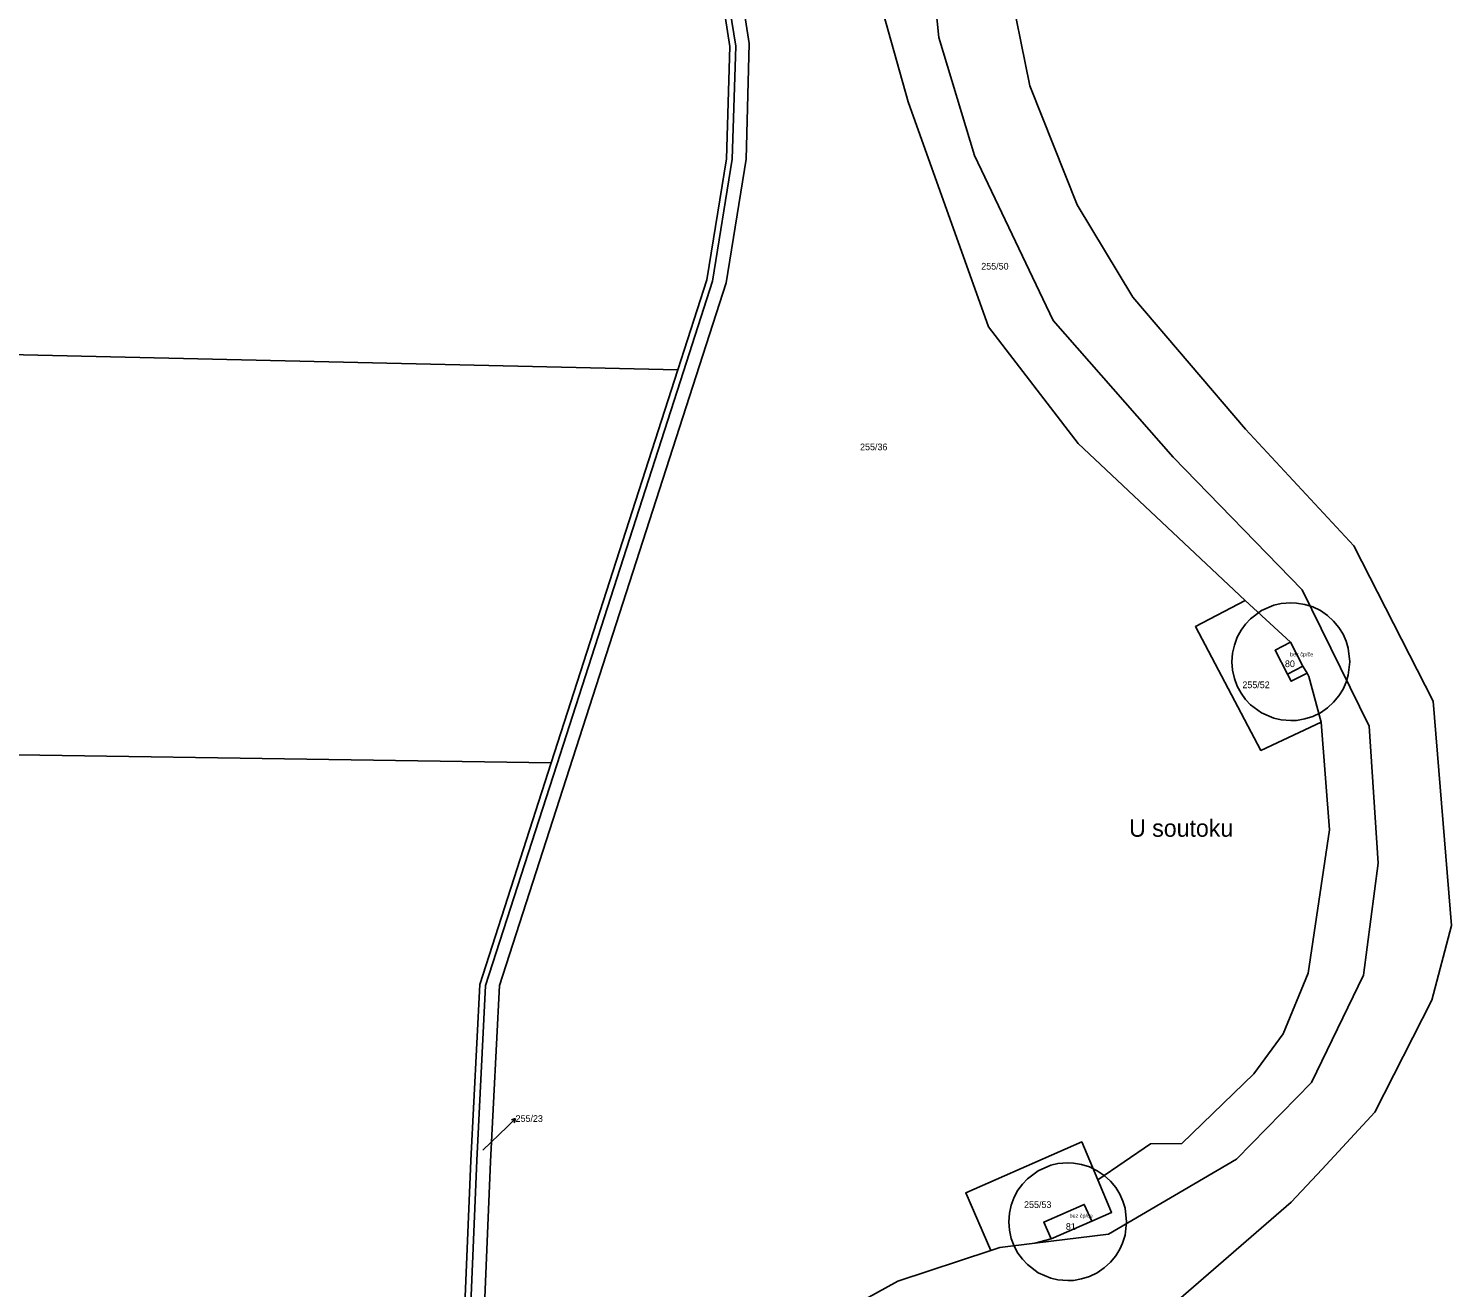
# Model space of a CAD drawing. Extents: x -882150 to -879379, y -1022570 to -1019819.
# Drawn here: x -880638.1 to -880276, y -1021896.3 to -1021575.9 of the extents above; entities that cross this region are included whole.
import ezdxf

# ---------------------------------------------------------------- set-up
doc = ezdxf.new("R2010")
doc.units = 0
for name, color, linetype in [('Definiční body', 7, 'Continuous'), ('Hranice parcel', 7, 'Continuous'), ('Parcelní čísla', 7, 'Continuous'), ('Polygon budovy', 7, 'Continuous'), ('Pop  PČ popisy', 7, 'Continuous'), ('Vnitřní kresba', 7, 'Continuous')]:
    doc.layers.add(name, color=color, linetype=linetype)

msp = doc.modelspace()

# ---------------------------------------------------------------- linework, layer by layer
at = {"layer": 'Hranice parcel'}
for p, q in [((-880472.9, -1021662.8), (-880505.13, -1021762.84)), ((-880316.92, -1021732.11), (-880328.46, -1021721.51)), ((-880275.96, -1021804.23), (-880280.95, -1021823.18)), ((-880377.84, -1021883.98), (-880367.53, -1021879.47)), ((-880377.84, -1021883.98), (-880382, -1021885.04))]:
    msp.add_line(p, q, dxfattribs=at)
for points in [[(-880533.86, -1022007.05), (-880523.29, -1021950.58), (-880522.43, -1021909.12), (-880520.53, -1021864.27), (-880518.3, -1021819.45), (-880460.57, -1021640.65), (-880455.51, -1021609.22), (-880454.71, -1021579.75), (-880473.1, -1021460.72)], [(-880403.68, -1021494.04), (-880408.13, -1021519.01), (-880409.49, -1021548.16), (-880406.41, -1021578.18), (-880397.35, -1021608.26), (-880377.39, -1021650.23), (-880346.77, -1021685.06), (-880313.96, -1021718.82), (-880296.93, -1021753.52), (-880294.62, -1021788.33), (-880298.33, -1021816.85), (-880311.6, -1021844.17), (-880330.67, -1021863.71), (-880363.25, -1021882.74), (-880382, -1021885.04)], [(-880466.28, -1021537.91), (-880459.65, -1021580.52), (-880460.51, -1021609.07), (-880465.51, -1021639.85), (-880472.9, -1021662.8)], [(-880275.96, -1021804.23), (-880280.6, -1021747.13), (-880300.81, -1021707.6), (-880328.37, -1021677.93), (-880357.11, -1021644.33), (-880371.23, -1021620.81), (-880383.32, -1021590.53), (-880388.97, -1021562.43)], [(-880328.46, -1021721.51), (-880371.01, -1021681.52), (-880393.83, -1021651.84), (-880414.22, -1021594.55), (-880422.16, -1021566.44)], [(-880472.9, -1021662.8), (-880672.83, -1021658.19), (-880872.75, -1021653.59)], [(-880328.46, -1021721.51), (-880341.15, -1021728.13), (-880324.49, -1021759.67), (-880309.1, -1021752.44)], [(-880316.92, -1021732.11), (-880320.86, -1021734.17), (-880317.71, -1021740.23), (-880316.75, -1021742.03), (-880312.73, -1021740.03)], [(-880312.73, -1021740.03), (-880313.77, -1021738.18), (-880316.92, -1021732.11)], [(-880309.1, -1021752.44), (-880312.25, -1021740.86), (-880312.73, -1021740.03)], [(-880365.98, -1021868.96), (-880352.57, -1021859.77), (-880344.62, -1021859.66), (-880326.26, -1021841.92), (-880318.82, -1021831.77), (-880312.45, -1021816.35), (-880307.02, -1021779.9), (-880309.1, -1021752.44)], [(-880889.89, -1021756.99), (-880697.51, -1021759.91), (-880505.13, -1021762.84)], [(-880505.13, -1021762.84), (-880523.29, -1021819.2), (-880525.52, -1021864.02), (-880527.43, -1021908.91), (-880528.29, -1021950.47), (-880532.51, -1021972.91)], [(-880280.95, -1021823.18), (-880295.5, -1021851.75), (-880308.92, -1021866.24)], [(-880393.19, -1021886.89), (-880399.61, -1021872.28), (-880370.08, -1021859.3), (-880365.98, -1021868.96)], [(-880308.92, -1021866.24), (-880316.75, -1021874.64), (-880345.49, -1021899.44), (-880362.19, -1021905.21), (-880391.36, -1021908.72), (-880413.46, -1021915.14), (-880439.14, -1021932.52), (-880458.37, -1021949.23)], [(-880365.98, -1021868.96), (-880362.47, -1021877.24), (-880367.53, -1021879.47)], [(-880367.53, -1021879.47), (-880369.45, -1021875.18), (-880379.73, -1021879.68), (-880377.84, -1021883.98)], [(-880481.62, -1021946.61), (-880466.63, -1021928.82), (-880438.87, -1021906.81), (-880416.85, -1021894.75), (-880393.19, -1021886.89)], [(-880382, -1021885.04), (-880390.89, -1021886.13), (-880393.19, -1021886.89)]]:
    msp.add_lwpolyline(points, dxfattribs=at)
at = {"layer": 'Polygon budovy'}
for points in [[(-880320.86, -1021734.17), (-880317.71, -1021740.23), (-880313.77, -1021738.18), (-880316.92, -1021732.11)], [(-880379.73, -1021879.68), (-880377.84, -1021883.98), (-880367.53, -1021879.47), (-880369.45, -1021875.18)]]:
    msp.add_lwpolyline(points, close=True, dxfattribs=at)
at = {"layer": 'Pop  PČ popisy'}
for p, q in [((-880516.33, -1021855.42), (-880514.171, -1021853.335)), ((-880514.171, -1021853.335), (-880515.24, -1021853.671)), ((-880514.171, -1021853.335), (-880514.544, -1021854.391)), ((-880522.49, -1021861.38), (-880516.33, -1021855.42))]:
    msp.add_line(p, q, dxfattribs=at)
at = {"layer": 'Vnitřní kresba'}
for p, q in [((-880458.15, -1021580.43), (-880476.6, -1021461.91)), ((-880459.01, -1021609.22), (-880458.15, -1021580.43)), ((-880464.05, -1021640.2), (-880459.01, -1021609.22)), ((-880471.47, -1021663.26), (-880464.05, -1021640.2)), ((-880503.7, -1021763.3), (-880471.47, -1021663.26)), ((-880327.1, -1021726.13), (-880324.34, -1021724.08)), ((-880324.34, -1021724.08), (-880321.18, -1021722.71)), ((-880321.18, -1021722.71), (-880319.36, -1021722.28)), ((-880319.36, -1021722.28), (-880316.84, -1021722.07)), ((-880316.84, -1021722.07), (-880315.39, -1021722.14)), ((-880315.39, -1021722.14), (-880313.32, -1021722.49)), ((-880313.32, -1021722.49), (-880311.28, -1021723.14)), ((-880311.28, -1021723.14), (-880309.34, -1021724.08)), ((-880309.34, -1021724.08), (-880307.55, -1021725.29)), ((-880329.53, -1021729.08), (-880328.38, -1021727.49)), ((-880328.38, -1021727.49), (-880327.1, -1021726.13)), ((-880307.55, -1021725.29), (-880305.97, -1021726.73)), ((-880305.97, -1021726.73), (-880304.64, -1021728.35)), ((-880331.23, -1021732.83), (-880330.5, -1021730.87)), ((-880330.5, -1021730.87), (-880329.53, -1021729.08)), ((-880304.64, -1021728.35), (-880303.57, -1021730.08)), ((-880303.57, -1021730.08), (-880302.77, -1021731.86)), ((-880331.84, -1021737.07), (-880331.69, -1021734.92)), ((-880331.69, -1021734.92), (-880331.23, -1021732.83)), ((-880302.77, -1021731.86), (-880302.23, -1021733.65)), ((-880302.23, -1021733.65), (-880301.84, -1021737.07)), ((-880331.69, -1021739.22), (-880331.84, -1021737.07)), ((-880317.71, -1021740.23), (-880313.77, -1021738.18)), ((-880301.84, -1021737.07), (-880302.23, -1021740.49)), ((-880331.23, -1021741.31), (-880331.69, -1021739.22)), ((-880330.5, -1021743.27), (-880331.23, -1021741.31)), ((-880302.77, -1021742.28), (-880303.57, -1021744.07)), ((-880302.23, -1021740.49), (-880302.77, -1021742.28)), ((-880329.53, -1021745.06), (-880330.5, -1021743.27)), ((-880328.38, -1021746.65), (-880329.53, -1021745.06)), ((-880304.64, -1021745.8), (-880305.97, -1021747.41)), ((-880303.57, -1021744.07), (-880304.64, -1021745.8)), ((-880327.1, -1021748.01), (-880328.38, -1021746.65)), ((-880324.34, -1021750.06), (-880327.1, -1021748.01)), ((-880307.55, -1021748.85), (-880309.34, -1021750.06)), ((-880305.97, -1021747.41), (-880307.55, -1021748.85)), ((-880321.18, -1021751.43), (-880324.34, -1021750.06)), ((-880319.36, -1021751.86), (-880321.18, -1021751.43)), ((-880316.84, -1021752.07), (-880319.36, -1021751.86)), ((-880315.39, -1021752), (-880316.84, -1021752.07)), ((-880313.32, -1021751.65), (-880315.39, -1021752)), ((-880311.28, -1021751), (-880313.32, -1021751.65)), ((-880309.34, -1021750.06), (-880311.28, -1021751)), ((-880521.8, -1021819.47), (-880503.7, -1021763.3)), ((-880524.02, -1021864.02), (-880521.8, -1021819.47)), ((-880525.93, -1021908.96), (-880524.02, -1021864.02)), ((-880381.14, -1021866.6), (-880377.98, -1021865.23)), ((-880377.98, -1021865.23), (-880376.17, -1021864.8)), ((-880376.17, -1021864.8), (-880373.64, -1021864.58)), ((-880373.64, -1021864.58), (-880372.19, -1021864.66)), ((-880372.19, -1021864.66), (-880370.12, -1021865.01)), ((-880370.12, -1021865.01), (-880368.09, -1021865.65)), ((-880368.09, -1021865.65), (-880366.15, -1021866.6)), ((-880385.19, -1021870.01), (-880383.9, -1021868.65)), ((-880383.9, -1021868.65), (-880381.14, -1021866.6)), ((-880366.15, -1021866.6), (-880364.36, -1021867.81)), ((-880364.36, -1021867.81), (-880362.78, -1021869.25)), ((-880362.78, -1021869.25), (-880361.44, -1021870.86)), ((-880387.3, -1021873.38), (-880386.33, -1021871.59)), ((-880386.33, -1021871.59), (-880385.19, -1021870.01)), ((-880361.44, -1021870.86), (-880360.38, -1021872.59)), ((-880360.38, -1021872.59), (-880359.58, -1021874.38)), ((-880388.48, -1021877.43), (-880388.03, -1021875.34)), ((-880388.03, -1021875.34), (-880387.3, -1021873.38)), ((-880359.58, -1021874.38), (-880359.04, -1021876.17)), ((-880359.04, -1021876.17), (-880358.65, -1021879.58)), ((-880388.64, -1021879.58), (-880388.48, -1021877.43)), ((-880388.48, -1021881.74), (-880388.64, -1021879.58)), ((-880358.65, -1021879.58), (-880359.04, -1021883)), ((-880388.03, -1021883.82), (-880388.48, -1021881.74)), ((-880359.04, -1021883), (-880359.69, -1021885.08)), ((-880387.3, -1021885.79), (-880388.03, -1021883.82)), ((-880386.33, -1021887.58), (-880387.3, -1021885.79)), ((-880360.38, -1021886.58), (-880361.44, -1021888.31)), ((-880359.69, -1021885.08), (-880360.38, -1021886.58)), ((-880385.19, -1021889.16), (-880386.33, -1021887.58)), ((-880383.9, -1021890.52), (-880385.19, -1021889.16)), ((-880381.14, -1021892.57), (-880383.9, -1021890.52)), ((-880362.78, -1021889.92), (-880364.36, -1021891.36)), ((-880361.44, -1021888.31), (-880362.78, -1021889.92)), ((-880377.98, -1021893.94), (-880381.14, -1021892.57)), ((-880376.17, -1021894.37), (-880377.98, -1021893.94)), ((-880373.64, -1021894.58), (-880376.17, -1021894.37)), ((-880372.19, -1021894.51), (-880373.64, -1021894.58)), ((-880370.12, -1021894.16), (-880372.19, -1021894.51)), ((-880368.09, -1021893.51), (-880370.12, -1021894.16)), ((-880366.15, -1021892.57), (-880368.09, -1021893.51)), ((-880364.36, -1021891.36), (-880366.15, -1021892.57))]:
    msp.add_line(p, q, dxfattribs=at)

# ---------------------------------------------------------------- texts
at = {"layer": 'Definiční body'}
for p in [(-880317.06, -1021735.7), (-880373.18, -1021878.56)]:
    msp.add_text('bez čp/če', height=1, dxfattribs=at).set_placement(p)
at = {"layer": 'Parcelní čísla'}
for s, p in [('255/50', (-880395.65, -1021637.28)), ('255/36', (-880426.49, -1021683.26)), ('80', (-880318.36, -1021738.45)), ('255/52', (-880329.19, -1021743.81)), ('255/23', (-880514.17, -1021854.18)), ('255/53', (-880384.75, -1021876.08)), ('81', (-880374.12, -1021881.66))]:
    msp.add_text(s, height=1.7, dxfattribs=at).set_placement(p)
at = {"layer": 'Pop  PČ popisy'}
msp.add_text('U soutoku', height=4.4, dxfattribs=at).set_placement((-880358.022, -1021781.62))

doc.saveas('drawing.dxf')
